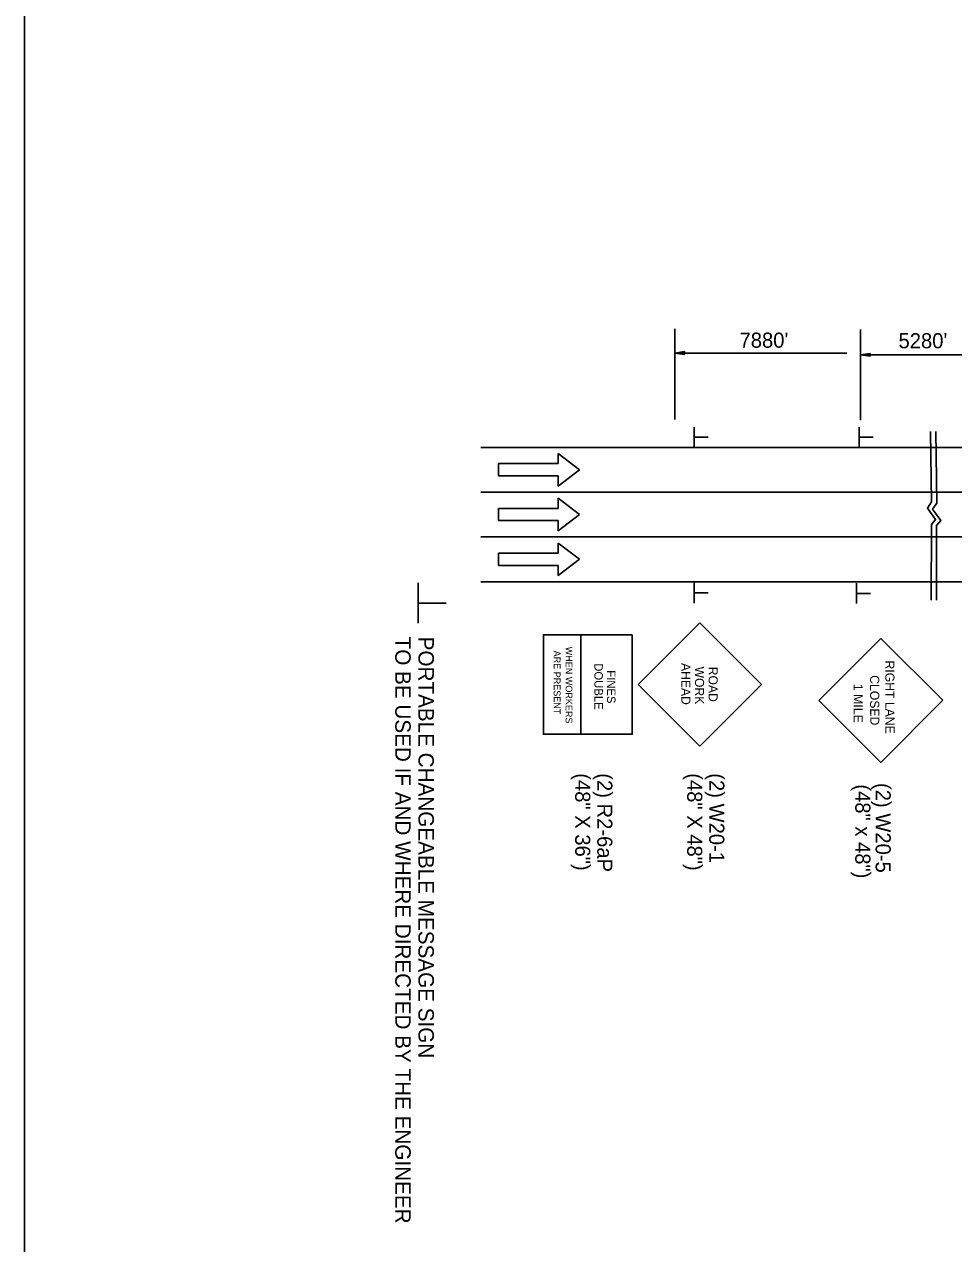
# Model space of a CAD drawing. Extents: x -100 to 745, y -1581 to -107.
# Drawn here: x 175.41 to 211.47, y -325.89 to -278.57 of the extents above; entities that cross this region are included whole.
import ezdxf

# ---------------------------------------------------------------- set-up
doc = ezdxf.new("R2010")
doc.units = 0
for name, color, linetype in [('Default', 7, 'Continuous'), ('R_Contour Annot', 7, 'Continuous'), ('R_Draft', 7, 'Continuous')]:
    doc.layers.add(name, color=color, linetype=linetype)

msp = doc.modelspace()

# ---------------------------------------------------------------- linework, layer by layer
at = {"layer": 'Default'}
for p, q in [((200.647, -290.39), (200.647, -293.911)), ((207.863, -290.419), (207.863, -293.94)), ((201.022, -291.275), (200.647, -291.332)), ((200.647, -291.332), (207.334, -291.332)), ((201.022, -291.388), (200.647, -291.332)), ((201.022, -291.285), (200.71, -291.332)), ((201.022, -291.379), (200.71, -291.332)), ((201.022, -291.294), (200.774, -291.332)), ((201.022, -291.369), (200.774, -291.332)), ((201.022, -291.304), (200.837, -291.332)), ((201.022, -291.36), (200.837, -291.332)), ((201.022, -291.313), (200.9, -291.332)), ((201.022, -291.35), (200.9, -291.332)), ((201.022, -291.323), (200.963, -291.332)), ((201.022, -291.34), (200.963, -291.332)), ((201.022, -291.388), (201.022, -291.275)), ((208.238, -291.342), (207.863, -291.398)), ((207.863, -291.398), (213.082, -291.398)), ((208.238, -291.455), (207.863, -291.398)), ((208.238, -291.351), (207.926, -291.398)), ((208.238, -291.445), (207.926, -291.398)), ((208.238, -291.361), (207.99, -291.398)), ((208.238, -291.436), (207.99, -291.398)), ((208.238, -291.37), (208.053, -291.398)), ((208.238, -291.426), (208.053, -291.398)), ((208.238, -291.38), (208.116, -291.398)), ((208.238, -291.417), (208.116, -291.398)), ((208.238, -291.39), (208.179, -291.398)), ((208.238, -291.407), (208.179, -291.398)), ((208.238, -291.455), (208.238, -291.342)), ((201.402, -294.984), (201.402, -294.202)), ((207.801, -294.984), (207.801, -294.202)), ((201.413, -294.595), (201.947, -294.595)), ((207.813, -294.595), (208.347, -294.595)), ((193.119, -294.99), (199.997, -294.99)), ((196.128, -295.227), (196.128, -295.622)), ((196.128, -295.227), (196.949, -295.859)), ((199.997, -294.99), (203.422, -294.99)), ((203.422, -294.99), (210.084, -294.99)), ((210.084, -294.99), (216.984, -294.99)), ((196.128, -295.622), (193.803, -295.622)), ((193.803, -295.622), (193.803, -296.097)), ((196.128, -296.097), (193.803, -296.097)), ((196.949, -295.859), (196.128, -296.492)), ((196.128, -296.097), (196.128, -296.492)), ((193.119, -296.729), (200.073, -296.729)), ((196.128, -296.966), (196.128, -297.361)), ((196.128, -296.966), (196.949, -297.598)), ((200.073, -296.729), (203.966, -296.729)), ((203.966, -296.729), (210.084, -296.729)), ((210.084, -296.729), (216.984, -296.729)), ((196.128, -297.361), (193.803, -297.361)), ((193.803, -297.361), (193.803, -297.835)), ((196.949, -297.598), (196.128, -298.23)), ((196.128, -297.835), (193.803, -297.835)), ((196.128, -297.835), (196.128, -298.23)), ((193.119, -298.467), (200.073, -298.467)), ((200.073, -298.467), (203.966, -298.467)), ((203.966, -298.467), (210.084, -298.467)), ((210.084, -298.467), (216.984, -298.467)), ((196.128, -298.704), (196.128, -299.099)), ((196.128, -298.704), (196.949, -299.336)), ((196.128, -299.099), (193.803, -299.099)), ((193.803, -299.099), (193.803, -299.574)), ((196.949, -299.336), (196.128, -299.969)), ((196.128, -299.574), (193.803, -299.574)), ((196.128, -299.574), (196.128, -299.969)), ((190.692, -301.81), (190.692, -300.246)), ((193.119, -300.206), (200.002, -300.206)), ((200.002, -300.206), (203.427, -300.206)), ((201.402, -301.032), (201.402, -300.25)), ((203.427, -300.206), (210.084, -300.206)), ((207.704, -301.049), (207.704, -300.266)), ((210.084, -300.206), (216.984, -300.206)), ((201.413, -300.643), (201.947, -300.643)), ((207.716, -300.66), (208.25, -300.66)), ((190.715, -301.032), (191.783, -301.032)), ((199.234, -304.197), (201.622, -301.806)), ((204.013, -304.197), (201.622, -301.806)), ((196.999, -306.128), (196.999, -302.266)), ((206.24, -304.816), (208.642, -302.406)), ((211.05, -304.807), (208.642, -302.406)), ((201.622, -306.587), (199.234, -304.197)), ((201.622, -306.587), (204.013, -304.197)), ((208.65, -307.217), (206.24, -304.816)), ((208.65, -307.217), (211.05, -304.807))]:
    msp.add_line(p, q, dxfattribs=at)
for points in [[(210.579, -294.379), (210.62, -297.11), (210.458, -297.352), (210.775, -297.785), (210.608, -297.985), (210.607, -300.92)], [(210.779, -294.376), (210.821, -297.152), (210.658, -297.393), (210.975, -297.826), (210.808, -298.026), (210.808, -300.917)]]:
    msp.add_lwpolyline(points, dxfattribs=at)
msp.add_lwpolyline([(199.001, -302.266), (195.549, -302.266), (195.549, -306.128), (199.001, -306.128)], close=True, dxfattribs=at)
at = {"layer": 'R_Contour Annot'}
msp.add_lwpolyline([(175.406, -260.582), (345.406, -260.582), (345.406, -370.582), (175.406, -370.582)], close=True, dxfattribs=at)
at = {"layer": 'R_Draft'}
msp.add_lwpolyline([(175.406, -260.582), (175.406, -370.582), (345.406, -370.582), (345.406, -260.582)], close=True, dxfattribs=at)

# ---------------------------------------------------------------- texts
at = {"layer": 'Default'}
for s, p in [("7880'", (203.163, -291.124)), ("5280'", (209.334, -291.145))]:
    msp.add_text(s, height=0.5862, dxfattribs=at).set_placement(p)
for s, height, rotation, p in [('TO BE USED IF AND WHERE DIRECTED BY THE ENGINEER', 0.59997, 270, (189.8, -302.338)), ('PORTABLE CHANGEABLE MESSAGE SIGN', 0.59997, 270, (190.7, -302.338)), ('WHEN WORKERS', 0.26221, 270, (196.413, -302.727)), ('ARE PRESENT', 0.26221, 270, (195.953, -302.879)), ('RIGHT LANE', 0.3544, 270.1004, (208.82, -303.262)), ('DOUBLE', 0.3278, 270, (197.53, -303.37)), ('FINES', 0.3278, 270, (198.021, -303.641)), ('AHEAD', 0.3522, 270.0006, (200.906, -303.361)), ('WORK', 0.352, 270, (201.435, -303.499)), ('ROAD', 0.3521, 270.0004, (201.963, -303.506)), ('1 MILE', 0.3567, 270.0006, (207.59, -304.17)), ('CLOSED', 0.3543, 270.1003, (208.231, -303.834)), ('(48" X 36")', 0.5862, 270, (196.784, -307.639)), ('(2) R2-6aP', 0.5862, 270, (197.641, -307.639)), ('(48" X 48")', 0.5862, 270, (201.131, -307.639)), ('(2) W20-1', 0.5862, 270, (201.988, -307.639)), ('(48" x 48")', 0.5862, 270, (207.656, -308.07)), ('(2) W20-5', 0.5862, 270, (208.446, -308.017))]:
    msp.add_text(s, height=height, rotation=rotation, dxfattribs=at).set_placement(p)

doc.saveas('drawing.dxf')
